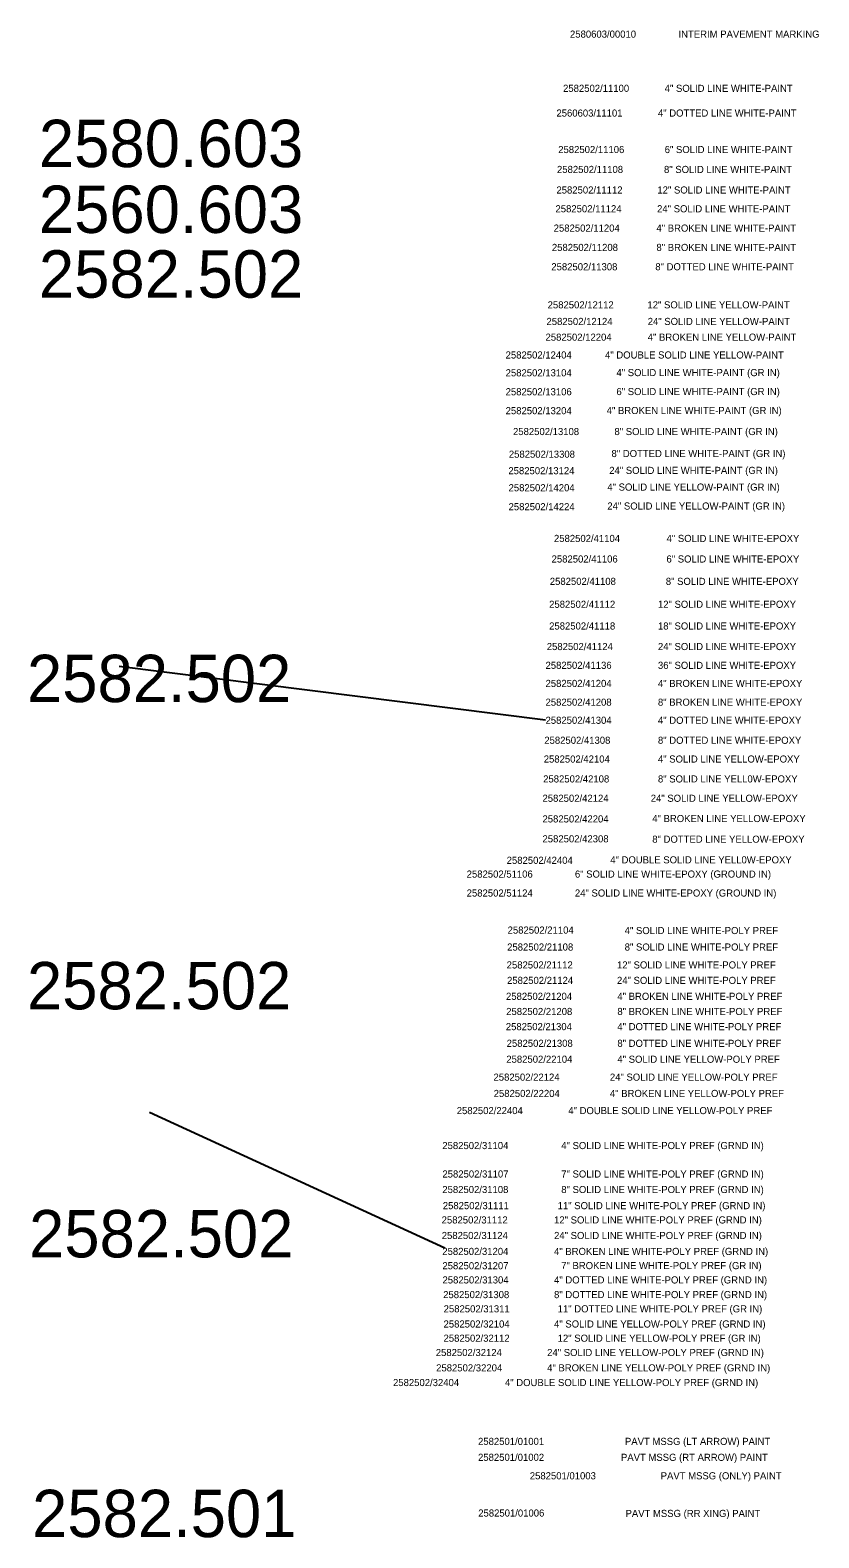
# Model space of a CAD drawing. Extents: x 2147716 to 2176321, y 2125040 to 2131750.
# Drawn here: x 2155873 to 2156706, y 2127858 to 2129449 of the extents above; entities that cross this region are included whole.
import ezdxf

# ---------------------------------------------------------------- set-up
doc = ezdxf.new("R2010")
doc.units = 0
doc.layers.add('DETAIL TXT', color=7, linetype='Continuous')
doc.layers.add('PVMT STRP', color=7, linetype='Continuous')

msp = doc.modelspace()

# ---------------------------------------------------------------- linework, layer by layer
at = {"layer": 'DETAIL TXT'}
for p, q in [((2156417.2, 2128721), (2155967.2, 2128777.8)), ((2156311.1, 2128163.9), (2155999.4, 2128307.2))]:
    msp.add_line(p, q, dxfattribs=at)

# ---------------------------------------------------------------- texts
for s, height, p in [('2580603/00010', 7.5, (2156443, 2129441.4)), ('INTERIM PAVEMENT MARKING', 7.5, (2156557.5, 2129441.4)), ('2582502/11100', 7.5, (2156435.7, 2129384.2)), ('4" SOLID LINE WHITE-PAINT', 7.5, (2156542.9, 2129384.2)), ('2560603/11101', 7.5, (2156428.7, 2129358.1)), ('4" DOTTED LINE WHITE-PAINT', 7.5, (2156535.8, 2129358.1)), ('2580.603', 50, (2155882.7, 2129304.8)), ('2582502/11106', 7.5, (2156430.6, 2129319.6)), ('6" SOLID LINE WHITE-PAINT', 7.5, (2156542.9, 2129319.6)), ('2582502/11108', 7.5, (2156429.3, 2129298.6)), ('8" SOLID LINE WHITE-PAINT', 7.5, (2156542.2, 2129298.6)), ('2560.603', 50, (2155882.7, 2129235.3)), ('2582502/11112', 7.5, (2156428.7, 2129276.9)), ('12" SOLID LINE WHITE-PAINT', 7.5, (2156535.2, 2129276.9)), ('2582502/11124', 7.5, (2156427.7, 2129257.1)), ('24" SOLID LINE WHITE-PAINT', 7.5, (2156534.9, 2129257.1)), ('2582502/11204', 7.5, (2156425.8, 2129236.7)), ('4" BROKEN LINE WHITE-PAINT', 7.5, (2156534.2, 2129236.7)), ('2582.502', 50, (2155882.7, 2129167)), ('2582502/11208', 7.5, (2156423.9, 2129216.3)), ('8" BROKEN LINE WHITE-PAINT', 7.5, (2156534.2, 2129216.3)), ('2582502/11308', 7.5, (2156423.3, 2129195.9)), ('8" DOTTED LINE WHITE-PAINT', 7.5, (2156533, 2129195.9)), ('2582502/12112', 7.5, (2156419.4, 2129155.7)), ('12" SOLID LINE YELLOW-PAINT', 7.5, (2156524.7, 2129155.7)), ('2582502/12124', 7.5, (2156418.2, 2129138.2)), ('24" SOLID LINE YELLOW-PAINT', 7.5, (2156525, 2129138.2)), ('2582502/12204', 7.5, (2156417.2, 2129121.6)), ('4" BROKEN LINE YELLOW-PAINT', 7.5, (2156525, 2129121.6)), ('2582502/12404', 7.5, (2156375.1, 2129102.8)), ('4" DOUBLE SOLID LINE YELLOW-PAINT', 7.5, (2156480, 2129102.8)), ('2582502/13104', 7.5, (2156375.1, 2129084)), ('4" SOLID LINE WHITE-PAINT (GR IN)', 7.5, (2156492, 2129084.2)), ('6" SOLID LINE WHITE-PAINT (GR IN)', 7.5, (2156492, 2129064.2)), ('2582502/13106', 7.5, (2156375.1, 2129064)), ('2582502/13204', 7.5, (2156375.1, 2129044)), ('4" BROKEN LINE WHITE-PAINT (GR IN)', 7.5, (2156481.7, 2129044.2)), ('2582502/13108', 7.5, (2156382.9, 2129022)), ('8" SOLID LINE WHITE-PAINT (GR IN)', 7.5, (2156489.9, 2129022)), ('2582502/13308', 7.5, (2156378.5, 2128998.1)), ('8" DOTTED LINE WHITE-PAINT (GR IN)', 7.5, (2156486.8, 2128998.8)), ('2582502/13124', 7.5, (2156378, 2128980.7)), ('24" SOLID LINE WHITE-PAINT (GR IN)', 7.5, (2156484.4, 2128981)), ('2582502/14204', 7.5, (2156378.2, 2128962.7)), ('4" SOLID LINE YELLOW-PAINT (GR IN)', 7.5, (2156482.4, 2128963.4)), ('2582502/14224', 7.5, (2156378.2, 2128942.7)), ('24" SOLID LINE YELLOW-PAINT (GR IN)', 7.5, (2156482.4, 2128943.4)), ('2582502/41104', 7.5, (2156426.1, 2128909.2)), ('4" SOLID LINE WHITE-EPOXY', 7.5, (2156544.9, 2128909.2)), ('2582502/41106', 7.5, (2156423.6, 2128887.5)), ('6" SOLID LINE WHITE-EPOXY', 7.5, (2156544.8, 2128887.5)), ('2582502/41108', 7.5, (2156421.7, 2128863.9)), ('8" SOLID LINE WHITE-EPOXY', 7.5, (2156544.1, 2128863.9)), ('2582502/41112', 7.5, (2156421, 2128839.7)), ('12" SOLID LINE WHITE-EPOXY', 7.5, (2156535.8, 2128839.7)), ('2582502/41118', 7.5, (2156421, 2128816.8)), ('18" SOLID LINE WHITE-EPOXY', 7.5, (2156535.8, 2128816.8)), ('2582502/41124', 7.5, (2156418.5, 2128795.1)), ('24" SOLID LINE WHITE-EPOXY', 7.5, (2156535.8, 2128795.1)), ('2582.502', 50, (2155870.1, 2128740.2)), ('2582502/41136', 7.5, (2156417.2, 2128775.3)), ('36" SOLID LINE WHITE-EPOXY', 7.5, (2156535.8, 2128775.3)), ('2582502/41204', 7.5, (2156417.2, 2128756.2)), ('4" BROKEN LINE WHITE-EPOXY', 7.5, (2156535.8, 2128756.2)), ('2582502/41208', 7.5, (2156417.2, 2128736.4)), ('8" BROKEN LINE WHITE-EPOXY', 7.5, (2156535.8, 2128736.4)), ('4" DOTTED LINE WHITE-EPOXY', 7.5, (2156535.8, 2128717.3)), ('2582502/41308', 7.5, (2156415.9, 2128696.2)), ('8" DOTTED LINE WHITE-EPOXY', 7.5, (2156535.8, 2128696.2)), ('2582502/42104', 7.5, (2156415.3, 2128676.4)), ('4" SOLID LINE YELLOW-EPOXY', 7.5, (2156535.8, 2128676.4)), ('2582502/42108', 7.5, (2156414.7, 2128655.4)), ('8" SOLID LINE YELL0W-EPOXY', 7.5, (2156535.8, 2128655.4)), ('2582502/42124', 7.5, (2156414, 2128635)), ('24" SOLID LINE YELLOW-EPOXY', 7.5, (2156528.2, 2128635)), ('2582502/42204', 7.5, (2156414, 2128613.2)), ('4" BROKEN LINE YELLOW-EPOXY', 7.5, (2156529.8, 2128613.6)), ('2582502/42308', 7.5, (2156414, 2128592.2)), ('8" DOTTED LINE YELLOW-EPOXY', 7.5, (2156529.8, 2128591.8)), ('2582502/42404', 7.5, (2156376.2, 2128569.5)), ('4" DOUBLE SOLID LINE YELL0W-EPOXY', 7.5, (2156485.5, 2128570)), ('2582502/51106', 7.5, (2156334, 2128555)), ('6" SOLID LINE WHITE-EPOXY (GROUND IN)', 7.5, (2156448.2, 2128555)), ('2582502/51124', 7.5, (2156334, 2128535)), ('24" SOLID LINE WHITE-EPOXY (GROUND IN)', 7.5, (2156448.2, 2128535)), ('2582502/21104', 7.5, (2156377.2, 2128495.9)), ('4" SOLID LINE WHITE-POLY PREF', 7.5, (2156500.7, 2128495.4)), ('2582502/21108', 7.5, (2156376.7, 2128478)), ('8" SOLID LINE WHITE-POLY PREF', 7.5, (2156500.7, 2128478)), ('2582.502', 50, (2155870.1, 2128416)), ('2582502/21112', 7.5, (2156376.2, 2128459.1)), ('12" SOLID LINE WHITE-POLY PREF', 7.5, (2156492.6, 2128459.1)), ('2582502/21124', 7.5, (2156376.6, 2128442.8)), ('24" SOLID LINE WHITE-POLY PREF', 7.5, (2156492.6, 2128442.8)), ('2582502/21204', 7.5, (2156375.5, 2128426)), ('4" BROKEN LINE WHITE-POLY PREF', 7.5, (2156493, 2128426)), ('2582502/21208', 7.5, (2156375.7, 2128410)), ('8" BROKEN LINE WHITE-POLY PREF', 7.5, (2156493, 2128410)), ('2582502/21304', 7.5, (2156375.3, 2128394)), ('4" DOTTED LINE WHITE-POLY PREF', 7.5, (2156493, 2128394)), ('2582502/21308', 7.5, (2156376.2, 2128376.4)), ('8" DOTTED LINE WHITE-POLY PREF', 7.5, (2156493, 2128376.4)), ('2582502/22104', 7.5, (2156375.8, 2128359.6)), ('4" SOLID LINE YELLOW-POLY PREF', 7.5, (2156493, 2128359.6)), ('2582502/22124', 7.5, (2156362.3, 2128340.7)), ('24" SOLID LINE YELLOW-POLY PREF', 7.5, (2156485.1, 2128340.7)), ('2582502/22204', 7.5, (2156362.5, 2128323.5)), ('4" BROKEN LINE YELLOW-POLY PREF', 7.5, (2156485.1, 2128323.5)), ('2582502/22404', 7.5, (2156323.5, 2128305.4)), ('4" DOUBLE SOLID LINE YELLOW-POLY PREF', 7.5, (2156441.2, 2128305.4)), ('2582502/31104', 7.5, (2156308.3, 2128268.5)), ('4" SOLID LINE WHITE-POLY PREF (GRND IN)', 7.5, (2156433.8, 2128268.5)), ('2582502/31107', 7.5, (2156308.4, 2128238.5)), ('7" SOLID LINE WHITE-POLY PREF (GRND IN)', 7.5, (2156433.8, 2128238.5)), ('2582502/31108', 7.5, (2156308.3, 2128222.1)), ('8" SOLID LINE WHITE-POLY PREF (GRND IN)', 7.5, (2156433.8, 2128222.1)), ('2582502/31111', 7.5, (2156308.8, 2128205.1)), ('11" SOLID LINE WHITE-POLY PREF (GRND IN)', 7.5, (2156430, 2128205.1)), ('2582.502', 50, (2155872.3, 2128154.2)), ('2582502/31112', 7.5, (2156307.6, 2128190)), ('12" SOLID LINE WHITE-POLY PREF (GRND IN)', 7.5, (2156426.2, 2128190)), ('2582502/31124', 7.5, (2156307.7, 2128173.6)), ('24" SOLID LINE WHITE-POLY PREF (GRND IN)', 7.5, (2156426.2, 2128173.6)), ('2582502/31204', 7.5, (2156308.3, 2128156.8)), ('4" BROKEN LINE WHITE-POLY PREF (GRND IN)', 7.5, (2156426.2, 2128156.8)), ('7" BROKEN LINE WHITE-POLY PREF (GR IN)', 7.5, (2156433.7, 2128141.8)), ('2582502/31304', 7.5, (2156308.5, 2128126.7)), ('4" DOTTED LINE WHITE-POLY PREF (GRND IN)', 7.5, (2156426.2, 2128126.7)), ('2582502/31308', 7.5, (2156309.2, 2128111.2)), ('8" DOTTED LINE WHITE-POLY PREF (GRND IN)', 7.5, (2156426.2, 2128111.2)), ('2582502/31311', 7.5, (2156309.7, 2128096.2)), ('11" DOTTED LINE WHITE-POLY PREF (GR IN)', 7.5, (2156430, 2128096.2)), ('2582502/32104', 7.5, (2156309.6, 2128080.2)), ('4" SOLID LINE YELLOW-POLY PREF (GRND IN)', 7.5, (2156426.2, 2128080.2)), ('2582502/32112', 7.5, (2156309.6, 2128065.2)), ('12" SOLID LINE YELLOW-POLY PREF (GR IN)', 7.5, (2156430, 2128065.2)), ('2582502/32124', 7.5, (2156301.4, 2128050.1)), ('24" SOLID LINE YELLOW-POLY PREF (GRND IN)', 7.5, (2156418.9, 2128050.1)), ('2582502/32204', 7.5, (2156301.8, 2128033.9)), ('4" BROKEN LINE YELLOW-POLY PREF (GRND IN)', 7.5, (2156418.9, 2128033.9)), ('2582502/32404', 7.5, (2156256.3, 2128018.4)), ('4" DOUBLE SOLID LINE YELLOW-POLY PREF (GRND IN)', 7.5, (2156374.4, 2128018.4)), ('2582501/01001', 7.5, (2156346, 2127956.3)), ('PAVT MSSG (LT ARROW) PAINT', 7.5, (2156501, 2127956.3)), ('2582501/01002', 7.5, (2156346, 2127939.5)), ('PAVT MSSG (RT ARROW) PAINT', 7.5, (2156496.8, 2127939.5)), ('2582501/01003', 7.5, (2156400.6, 2127920)), ('PAVT MSSG (ONLY) PAINT', 7.5, (2156538.7, 2127920)), ('2582.501', 50, (2155875.5, 2127859)), ('2582501/01006', 7.5, (2156346.2, 2127880.7)), ('PAVT MSSG (RR XING) PAINT', 7.5, (2156501.6, 2127880.3))]:
    msp.add_text(s, height=height, dxfattribs=at).set_placement(p)
at = {"layer": 'PVMT STRP'}
for s, p in [('2582502/41304', (2156417.2, 2128717.3)), ('2582502/31207', (2156308.4, 2128141.7))]:
    msp.add_text(s, height=7.5, dxfattribs=at).set_placement(p)

doc.saveas('drawing.dxf')
